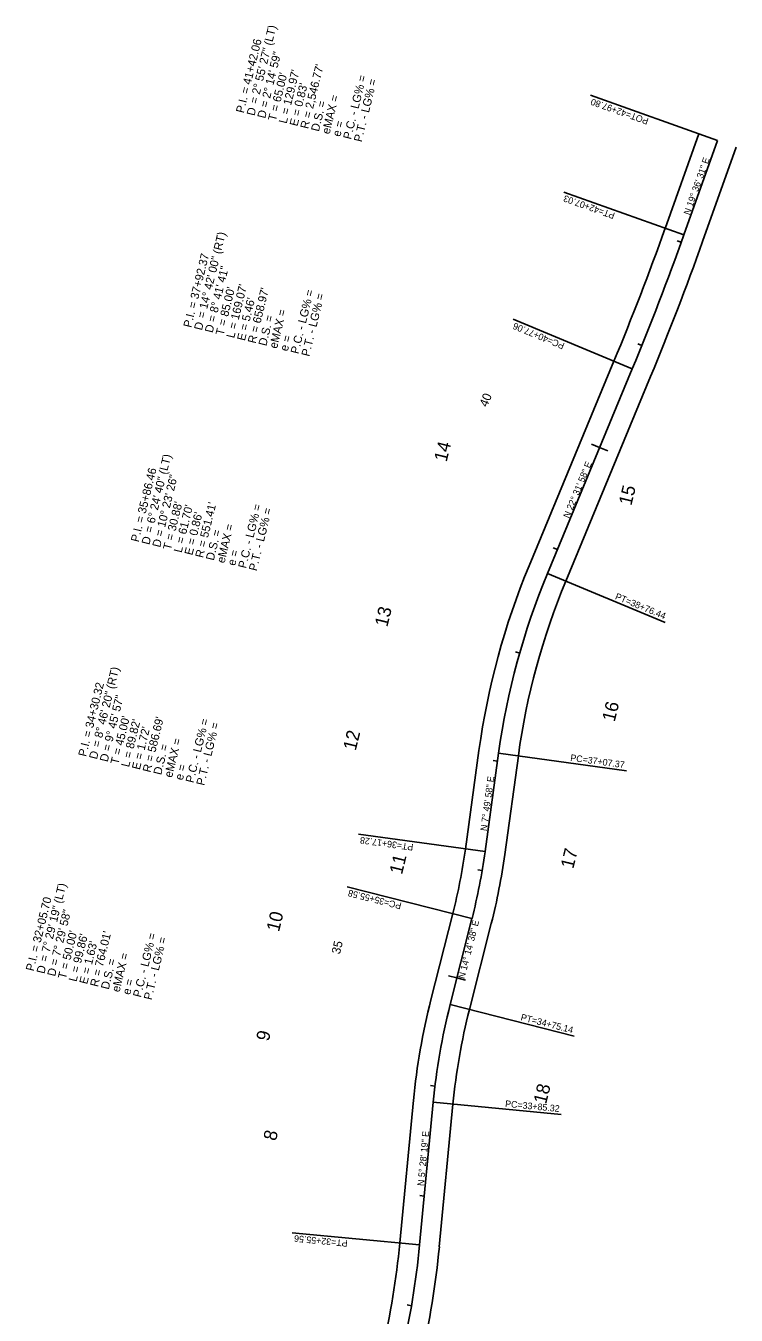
# Model space of a CAD drawing. Extents: x 1579440 to 1580937, y 1116374 to 1119566.
# Drawn here: x 1580144 to 1580787, y 1118399 to 1119566 of the extents above; entities that cross this region are included whole.
import ezdxf

# ---------------------------------------------------------------- set-up
doc = ezdxf.new("R2010")
doc.units = 0
for name, color, linetype in [('RD_EX_DV_TX_Prop', 7, 'Continuous'), ('RD_EX_RW', 7, 'Continuous'), ('RD_HC_Cl', 7, 'Continuous'), ('RD_HC_Data', 7, 'Continuous'), ('RD_HC_Data_Tic', 7, 'Continuous'), ('RD_HC_TX_Sta50', 7, 'Continuous')]:
    doc.layers.add(name, color=color, linetype=linetype)

msp = doc.modelspace()

# ---------------------------------------------------------------- linework, layer by layer
at = {"layer": 'RD_EX_RW'}
for p, q in [((1580722.9, 1119382.9), (1580753.4, 1119468.5)), ((1580756.8, 1119370.9), (1580787.3, 1119456.4)), ((1580599.7, 1119077.2), (1580676.5, 1119262.5)), ((1580632.9, 1119063.4), (1580709.8, 1119248.7)), ((1580542, 1118820.8), (1580554.3, 1118910.1)), ((1580577.7, 1118815.9), (1580590, 1118905.2)), ((1580510.8, 1118684.3), (1580530.6, 1118762.3)), ((1580545.7, 1118675.4), (1580565.5, 1118753.4)), ((1580482.6, 1118464), (1580495, 1118593.2)), ((1580518.4, 1118460.6), (1580530.8, 1118589.7))]:
    msp.add_line(p, q, dxfattribs=at)
for centre, radius, start, end in [((1578340.8, 1120231.6), 2528.8, 337.4673, 340.3913), ((1578340.8, 1120231.6), 2564.8, 337.4673, 340.3913), ((1581225, 1118817.8), 677, 157.4673, 172.1672), ((1581225, 1118817.8), 641, 157.4673, 172.1672), ((1580013.6, 1118893.5), 533.4, 345.756, 352.1672), ((1580013.6, 1118893.5), 569.4, 345.756, 352.1672), ((1581096.9, 1118535.5), 604.7, 165.756, 174.5281), ((1581096.9, 1118535.5), 568.7, 165.756, 174.5281), ((1579740, 1118535.1), 746, 347.0395, 354.5281), ((1579740, 1118535.1), 782, 347.0395, 354.5281)]:
    msp.add_arc(centre, radius, start, end, dxfattribs=at)
at = {"layer": 'RD_HC_Cl'}
for p, q in [((1580739.9, 1119376.9), (1580770.4, 1119462.4)), ((1580739.9, 1119376.9), (1580770.4, 1119462.4)), ((1580616.3, 1119070.3), (1580693.2, 1119255.6)), ((1580616.3, 1119070.3), (1580693.2, 1119255.6)), ((1580559.9, 1118818.4), (1580572.1, 1118907.6)), ((1580559.9, 1118818.4), (1580572.1, 1118907.6)), ((1580528.3, 1118679.9), (1580548, 1118757.8)), ((1580528.3, 1118679.9), (1580548, 1118757.8)), ((1580500.5, 1118462.3), (1580512.9, 1118591.5)), ((1580500.5, 1118462.3), (1580512.9, 1118591.5))]:
    msp.add_line(p, q, dxfattribs=at)
for centre, radius, start, end in [((1578340.8, 1120231.6), 2546.8, 337.4673, 340.3913), ((1578340.8, 1120231.6), 2546.8, 337.4673, 340.3913), ((1581225, 1118817.8), 659, 157.4673, 172.1672), ((1581225, 1118817.8), 659, 157.4673, 172.1672), ((1580013.6, 1118893.5), 551.4, 345.756, 352.1672), ((1580013.6, 1118893.5), 551.4, 345.756, 352.1672), ((1581096.9, 1118535.5), 586.7, 165.756, 174.5281), ((1581096.9, 1118535.5), 586.7, 165.756, 174.5281), ((1579740, 1118535.1), 764, 347.0395, 354.5281), ((1579740, 1118535.1), 764, 347.0395, 354.5281)]:
    msp.add_arc(centre, radius, start, end, dxfattribs=at)
at = {"layer": 'RD_HC_Data'}
for p, q in [((1580770.4, 1119462.4), (1580655.4, 1119503.4)), ((1580739.9, 1119376.9), (1580631.1, 1119415.7)), ((1580693.2, 1119255.6), (1580585.2, 1119300.5)), ((1580616.3, 1119070.3), (1580723.1, 1119026)), ((1580572.1, 1118907.6), (1580688, 1118891.7)), ((1580559.9, 1118818.4), (1580445.2, 1118834.1)), ((1580548, 1118757.8), (1580434.9, 1118786.6)), ((1580528.3, 1118679.9), (1580640.4, 1118651.4)), ((1580512.9, 1118591.5), (1580628.9, 1118580.3)), ((1580500.5, 1118462.3), (1580385.1, 1118473.3))]:
    msp.add_line(p, q, dxfattribs=at)
at = {"layer": 'RD_HC_Data_Tic'}
for p, q in [((1580737.5, 1119370.3), (1580733.8, 1119371.6)), ((1580701.9, 1119276.9), (1580698.2, 1119278.4)), ((1580663.6, 1119184.5), (1580656.3, 1119187.5)), ((1580671, 1119181.4), (1580663.6, 1119184.5)), ((1580625.3, 1119092.1), (1580621.6, 1119093.6)), ((1580591.2, 1118998.2), (1580587.3, 1118999.3)), ((1580571.1, 1118900.3), (1580567.2, 1118900.9)), ((1580557.2, 1118801.3), (1580553.3, 1118802)), ((1580534.4, 1118704), (1580526.6, 1118705.9)), ((1580542.1, 1118702), (1580534.4, 1118704)), ((1580514.5, 1118606.1), (1580510.5, 1118606.5)), ((1580504.8, 1118506.5), (1580500.8, 1118506.9)), ((1580493.2, 1118407.2), (1580489.3, 1118407.9))]:
    msp.add_line(p, q, dxfattribs=at)

# ---------------------------------------------------------------- texts
at = {"layer": 'RD_EX_DV_TX_Prop'}
for s, p in [('14', (1580525, 1119170.8)), ('15', (1580692.3, 1119131.2)), ('13', (1580471.3, 1119021.3)), ('16', (1580677.2, 1118935.4)), ('12', (1580442.7, 1118909.3)), ('17', (1580639.7, 1118802.3)), ('11', (1580484.6, 1118797.1)), ('10', (1580373.2, 1118745.2)), ('9', (1580363.9, 1118646.1)), ('18', (1580615.1, 1118589.2)), ('8', (1580370.4, 1118555.9))]:
    msp.add_text(s, height=12, rotation=76.2368, dxfattribs=at).set_placement(p)
at = {"layer": 'RD_HC_Data'}
for s, height, rotation, p in [('    = 2%%d 55\' 27" (LT)', 7.5, 76.2368, (1580351, 1119484.4)), ('P.I. = 41+42.06', 7.5, 76.2368, (1580341.3, 1119486.8)), ('D = 2%%d 14\' 59"', 7.5, 76.2368, (1580360.7, 1119482)), ("R = 2,546.77'", 7.5, 76.2368, (1580399.6, 1119472.5)), ("T = 65.00'", 7.5, 76.2368, (1580370.4, 1119479.6)), ("L = 129.97'", 7.5, 76.2368, (1580380.1, 1119477.3)), ('P.C. - LG% = ', 7.5, 76.2368, (1580438.4, 1119463)), ('P.T. - LG% = ', 7.5, 76.2368, (1580448.1, 1119460.6)), ("E = 0.83'", 7.5, 76.2368, (1580389.9, 1119474.9)), ('D.S. = ', 7.5, 76.2368, (1580409.3, 1119470.1)), ('eMAX = ', 7.5, 76.2368, (1580419, 1119467.7)), ('POT=42+97.80', 6, 160.3913, (1580708.5, 1119482.3)), ('D', 7.5, 76.2368, (1580351, 1119484.4)), ('e = ', 7.5, 76.2368, (1580428.7, 1119465.4)), ('N 19%%d 36\' 31" E', 6, 70.3913, (1580745.1, 1119394.5)), ('PT=42+07.03', 6, 160.3913, (1580678, 1119396.8)), ('    = 14%%d 42\' 00" (RT)', 7.5, 76.2368, (1580303.4, 1119290.1)), ('P.I. = 37+92.37', 7.5, 76.2368, (1580293.7, 1119292.5)), ('D = 8%%d 41\' 41"', 7.5, 76.2368, (1580313.1, 1119287.8)), ("T = 85.00'", 7.5, 76.2368, (1580322.9, 1119285.4)), ("L = 169.07'", 7.5, 76.2368, (1580332.6, 1119283)), ("E = 5.46'", 7.5, 76.2368, (1580342.3, 1119280.6)), ("R = 658.97'", 7.5, 76.2368, (1580352, 1119278.2)), ('P.C. - LG% = ', 7.5, 76.2368, (1580390.8, 1119268.7)), ('P.T. - LG% = ', 7.5, 76.2368, (1580400.6, 1119266.4)), ('eMAX = ', 7.5, 76.2368, (1580371.4, 1119273.5)), ('D', 7.5, 76.2368, (1580303.4, 1119290.1)), ('D.S. = ', 7.5, 76.2368, (1580361.7, 1119275.9)), ('PC=40+77.06', 6, 157.4673, (1580632.4, 1119278.7)), ('e = ', 7.5, 76.2368, (1580381.1, 1119271.1)), ('    = 6%%d 24\' 40" (LT)', 7.5, 76.2368, (1580255.8, 1119095.9)), ('N 22%%d 31\' 58" E', 6, 67.4673, (1580635.9, 1119119.9)), ('P.I. = 35+86.46', 7.5, 76.2368, (1580246.1, 1119098.3)), ('D = 10%%d 23\' 26"', 7.5, 76.2368, (1580265.6, 1119093.5)), ("T = 30.88'", 7.5, 76.2368, (1580275.3, 1119091.1)), ("L = 61.70'", 7.5, 76.2368, (1580285, 1119088.7)), ("R = 551.41'", 7.5, 76.2368, (1580304.4, 1119084)), ('P.C. - LG% = ', 7.5, 76.2368, (1580343.3, 1119074.5)), ("E = 0.86'", 7.5, 76.2368, (1580294.7, 1119086.4)), ('P.T. - LG% = ', 7.5, 76.2368, (1580353, 1119072.1)), ('D.S. = ', 7.5, 76.2368, (1580314.1, 1119081.6)), ('eMAX = ', 7.5, 76.2368, (1580323.8, 1119079.2)), ('D', 7.5, 76.2368, (1580255.8, 1119095.9)), ('e = ', 7.5, 76.2368, (1580333.5, 1119076.9)), ('PT=38+76.44', 6, 337.4673, (1580677.1, 1119047.3)), ('    = 8%%d 46\' 20" (RT)', 7.5, 76.2368, (1580208.3, 1118901.6)), ('P.I. = 34+30.32', 7.5, 76.2368, (1580198.5, 1118904)), ('D = 9%%d 45\' 57"', 7.5, 76.2368, (1580218, 1118899.2)), ("T = 45.00'", 7.5, 76.2368, (1580227.7, 1118896.9)), ("L = 89.82'", 7.5, 76.2368, (1580237.4, 1118894.5)), ("R = 586.69'", 7.5, 76.2368, (1580256.8, 1118889.7)), ('P.C. - LG% = ', 7.5, 76.2368, (1580295.7, 1118880.2)), ('P.T. - LG% = ', 7.5, 76.2368, (1580305.4, 1118877.8)), ("E = 1.72'", 7.5, 76.2368, (1580247.1, 1118892.1)), ('D', 7.5, 76.2368, (1580208.3, 1118901.6)), ('D.S. = ', 7.5, 76.2368, (1580266.5, 1118887.4)), ('eMAX = ', 7.5, 76.2368, (1580276.3, 1118885)), ('PC=37+07.37', 6, 352.1672, (1580636.8, 1118900.7)), ('e = ', 7.5, 76.2368, (1580286, 1118882.6)), ('N 7%%d 49\' 58" E', 6, 82.1672, (1580561.4, 1118836.8)), ('PT=36+17.28', 6, 172.1672, (1580495.2, 1118825.2)), ('    = 7%%d 29\' 19" (LT)', 7.5, 76.2368, (1580160.7, 1118707.4)), ('PC=35+55.58', 6, 165.756, (1580484.6, 1118771.9)), ('P.I. = 32+05.70', 7.5, 76.2368, (1580151, 1118709.7)), ('D = 7%%d 29\' 58"', 7.5, 76.2368, (1580170.4, 1118705)), ("T = 50.00'", 7.5, 76.2368, (1580180.1, 1118702.6)), ("R = 764.01'", 7.5, 76.2368, (1580209.2, 1118695.5)), ('N 14%%d 14\' 38" E', 6, 75.756, (1580541.2, 1118702.8)), ("L = 99.86'", 7.5, 76.2368, (1580189.8, 1118700.2)), ("E = 1.63'", 7.5, 76.2368, (1580199.5, 1118697.9)), ('P.C. - LG% = ', 7.5, 76.2368, (1580248.1, 1118686)), ('P.T. - LG% = ', 7.5, 76.2368, (1580257.8, 1118683.6)), ('eMAX = ', 7.5, 76.2368, (1580228.7, 1118690.7)), ('D', 7.5, 76.2368, (1580160.7, 1118707.4)), ('D.S. = ', 7.5, 76.2368, (1580219, 1118693.1)), ('e = ', 7.5, 76.2368, (1580238.4, 1118688.3)), ('PT=34+75.14', 6, 345.756, (1580591.7, 1118665.8)), ('PC=33+85.32', 6, 354.5281, (1580577.8, 1118587.3)), ('N 5%%d 28\' 19" E', 6, 84.5281, (1580504.5, 1118515.4)), ('PT=32+55.56', 6, 174.5281, (1580435.6, 1118466.5))]:
    msp.add_text(s, height=height, rotation=rotation, dxfattribs=at).set_placement(p)
at = {"layer": 'RD_HC_TX_Sta50'}
for s, rotation, p in [('40', 67.4673, (1580561.7, 1119220.5)), ('35', 75.756, (1580428.3, 1118725))]:
    msp.add_text(s, height=8, rotation=rotation, dxfattribs=at).set_placement(p)

doc.saveas('drawing.dxf')
